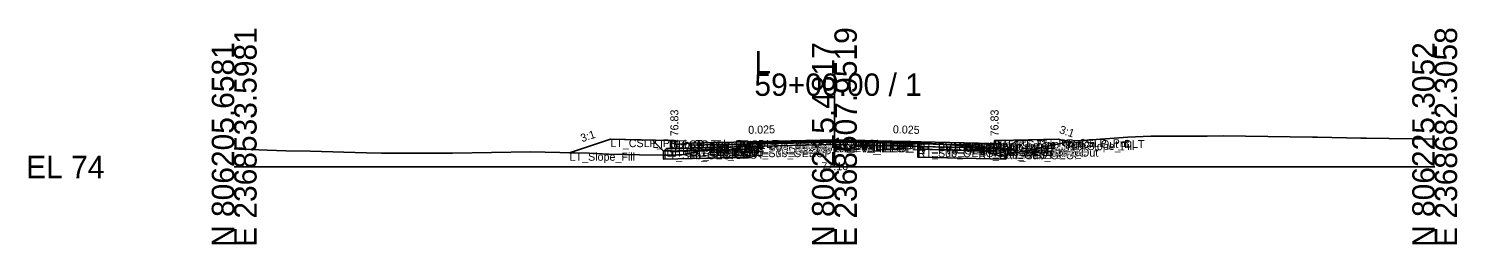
# Model space of a CAD drawing. Extents: x -26 to 8153, y -10 to 9520.
# Drawn here: x 4974.3 to 5152.8, y 7990.3 to 8017.3 of the extents above; entities that cross this region are included whole.
import ezdxf

# ---------------------------------------------------------------- set-up
doc = ezdxf.new("R2010")
doc.units = 0
for name, color, linetype in [('Exist CMT Pavement', 7, 'Continuous'), ('Exist Cross Section Cell', 7, 'Continuous'), ('Exist XS Center Line Elevation Label', 7, 'Continuous'), ('Exist XS Ground Line', 7, 'Continuous'), ('Prop CMT Conc Surface', 7, 'Continuous'), ('Prop CMT Concrete Structures', 7, 'Continuous'), ('Prop CMT Pvmt Course 1', 7, 'Continuous'), ('Prop CMT Pvmt Course 1 CG', 7, 'Continuous'), ('Prop CMT Pvmt Course 1 Wedge', 7, 'Continuous'), ('Prop CMT Pvmt Course 2', 7, 'Continuous'), ('Prop CMT Pvmt Course 2 Wedge', 7, 'Continuous'), ('Prop CMT Pvmt Course 3', 7, 'Continuous'), ('Prop CMT Pvmt Course 3 Wedge', 7, 'Continuous'), ('Prop CMT Pvmt Surface', 7, 'Continuous'), ('Prop CMT Pvmt Wedge Surface 1', 7, 'Continuous'), ('Prop CMT Pvmt Wedge Surface 2', 7, 'Continuous'), ('Prop CMT Pvmt Wedge Surface 3', 7, 'Continuous'), ('Prop CMT Shallow Undercut', 7, 'Continuous'), ('Prop CMT Shallow Undercut Boundary', 7, 'Continuous'), ('Prop CMT Slope Grass', 7, 'Continuous'), ('Prop CMT Subgrade Earthwork', 7, 'Continuous'), ('Prop XS Earthwork Shape', 7, 'Continuous'), ('Prop XS Hydro Elevations', 7, 'Continuous'), ('Prop XS SE Text', 7, 'Continuous'), ('Prop XS Side Slope Text', 7, 'Continuous'), ('Prop XS Subgrade Earthwork', 7, 'Continuous'), ('Scratch_Level_2', 7, 'Continuous'), ('Scratch_Level_6', 7, 'Continuous')]:
    doc.layers.add(name, color=color, linetype=linetype)

msp = doc.modelspace()

# ---------------------------------------------------------------- linework, layer by layer
at = {"layer": 'Exist CMT Pavement'}
for p, q in [((5064.44, 8002.84), (5073.5, 8003.08)), ((5073.5, 8003.08), (5074.68, 8003.11)), ((5074.68, 8003.11), (5075, 8003.1)), ((5075, 8003.1), (5075.67, 8003.1)), ((5075.67, 8003.1), (5085.41, 8003.05))]:
    msp.add_line(p, q, dxfattribs=at)
at = {"layer": 'Exist Cross Section Cell'}
for p, q in [((5075, 8000), (5075, 8011.7)), ((5000, 8000), (5075, 8000)), ((5075, 8000), (5150, 8000))]:
    msp.add_line(p, q, dxfattribs=at)
at = {"layer": 'Exist XS Ground Line'}
for p, q in [((5106.01, 8003.33), (5111.65, 8003.71)), ((5111.65, 8003.71), (5114.55, 8003.84)), ((5114.55, 8003.84), (5121.56, 8003.86)), ((5121.56, 8003.86), (5123.55, 8003.9)), ((5123.55, 8003.9), (5134.72, 8003.73)), ((5134.72, 8003.73), (5135.36, 8003.72)), ((5135.36, 8003.72), (5140.79, 8003.62)), ((5000, 8002.26), (5004.11, 8002.1)), ((5004.11, 8002.1), (5006.47, 8002.03)), ((5006.47, 8002.03), (5009.5, 8001.98)), ((5009.5, 8001.98), (5016.55, 8001.75)), ((5027.28, 8001.72), (5037.01, 8001.91)), ((5037.01, 8001.91), (5044.35, 8001.71)), ((5055.92, 8001.53), (5059.21, 8002.22)), ((5059.21, 8002.22), (5061.62, 8002.83)), ((5061.62, 8002.83), (5064.07, 8002.83)), ((5064.07, 8002.83), (5064.44, 8002.84)), ((5064.44, 8002.84), (5073.5, 8003.08)), ((5073.5, 8003.08), (5074.68, 8003.11)), ((5074.68, 8003.11), (5075, 8003.1)), ((5075, 8003.1), (5075.67, 8003.1)), ((5075.67, 8003.1), (5085.41, 8003.05)), ((5085.41, 8003.05), (5090, 8002.71)), ((5090, 8002.71), (5091.85, 8002.59)), ((5091.85, 8002.59), (5092.6, 8002.44)), ((5092.6, 8002.44), (5094.17, 8001.9)), ((5094.17, 8001.9), (5095.77, 8001.33)), ((5097.4, 8001.71), (5100.23, 8002.33)), ((5100.23, 8002.33), (5102.07, 8002.7)), ((5102.07, 8002.7), (5103.26, 8002.93)), ((5103.26, 8002.93), (5104.8, 8003.29)), ((5104.8, 8003.29), (5106.01, 8003.33)), ((5140.79, 8003.62), (5141.49, 8003.61)), ((5141.49, 8003.61), (5150, 8003.5)), ((5016.55, 8001.75), (5018.41, 8001.74)), ((5018.41, 8001.74), (5026.64, 8001.73)), ((5026.64, 8001.73), (5027.28, 8001.72)), ((5044.35, 8001.71), (5046.82, 8001.62)), ((5046.82, 8001.62), (5050.64, 8001.54)), ((5050.64, 8001.54), (5054.33, 8001.47)), ((5054.33, 8001.47), (5055.32, 8001.51)), ((5055.32, 8001.51), (5055.92, 8001.53)), ((5095.77, 8001.33), (5097.4, 8001.71))]:
    msp.add_line(p, q, dxfattribs=at)
at = {"layer": 'Prop CMT Conc Surface'}
for points in [[(5055, 8002.83), (5055, 8003.33), (5054.5, 8003.33)], [(5057, 8002.96), (5055, 8002.83)], [(5093, 8002.96), (5095, 8002.83)], [(5095, 8002.83), (5095, 8003.33), (5095.5, 8003.33)]]:
    msp.add_lwpolyline(points, dxfattribs=at)
at = {"layer": 'Prop CMT Concrete Structures'}
for points in [[(5057, 8002.96), (5055, 8002.83), (5055, 8003.33), (5054.5, 8003.33)], [(5054.5, 8003.33), (5054.5, 8002.31), (5057, 8002.37)], [(5057, 8002.37), (5057, 8002.96)], [(5093, 8002.96), (5095, 8002.83), (5095, 8003.33), (5095.5, 8003.33)], [(5095.5, 8003.33), (5095.5, 8002.31), (5093, 8002.37)], [(5093, 8002.37), (5093, 8002.96)]]:
    msp.add_lwpolyline(points, dxfattribs=at)
at = {"layer": 'Prop CMT Pvmt Course 1'}
for points in [[(5075, 8003.41), (5057, 8002.96)], [(5057, 8002.96), (5057, 8002.71)], [(5057, 8002.71), (5064.44, 8002.89)], [(5064.44, 8003.02), (5075, 8003.28)], [(5064.44, 8002.89), (5064.44, 8003.02)], [(5075, 8003.16), (5075, 8003.41)], [(5075, 8003.41), (5093, 8002.96)], [(5075, 8003.16), (5075, 8003.41)], [(5075, 8003.28), (5075, 8003.16), (5075, 8003.16)], [(5085.41, 8003.02), (5075, 8003.28)], [(5075, 8003.28), (5075, 8003.16), (5075, 8003.16)], [(5085.41, 8002.9), (5085.41, 8003.02)], [(5093, 8002.71), (5085.41, 8002.9)], [(5093, 8002.96), (5093, 8002.71)]]:
    msp.add_lwpolyline(points, dxfattribs=at)
at = {"layer": 'Prop CMT Pvmt Course 1 CG'}
for points in [[(5057, 8002.37), (5054, 8002.3), (5053.66, 8001.96)], [(5053.66, 8001.96), (5057, 8002.04)], [(5057, 8002.04), (5057, 8002.37)], [(5093, 8002.37), (5096, 8002.3), (5096.34, 8001.96)], [(5093, 8002.04), (5093, 8002.37)], [(5096.34, 8001.96), (5093, 8002.04)]]:
    msp.add_lwpolyline(points, dxfattribs=at)
at = {"layer": 'Prop CMT Pvmt Course 1 Wedge'}
for points in [[(5075, 8003.28), (5064.44, 8003.02)], [(5075, 8003.28), (5085.41, 8003.02)]]:
    msp.add_lwpolyline(points, dxfattribs=at)
at = {"layer": 'Prop CMT Pvmt Course 2'}
for points in [[(5064.44, 8002.89), (5057, 8002.71)], [(5057, 8002.71), (5057, 8002.38)], [(5057, 8002.38), (5064.44, 8002.56)], [(5064.44, 8002.56), (5064.44, 8002.89)], [(5085.41, 8002.57), (5085.41, 8002.9)], [(5085.41, 8002.9), (5093, 8002.71)], [(5093, 8002.38), (5085.41, 8002.57)], [(5093, 8002.71), (5093, 8002.38)]]:
    msp.add_lwpolyline(points, dxfattribs=at)
at = {"layer": 'Prop CMT Pvmt Course 2 Wedge'}
for points in [[(5075, 8003.16), (5064.44, 8002.89)], [(5075, 8003.16), (5085.41, 8002.9)]]:
    msp.add_lwpolyline(points, dxfattribs=at)
at = {"layer": 'Prop CMT Pvmt Course 3'}
for points in [[(5064.44, 8002.56), (5057, 8002.38)], [(5057, 8002.38), (5057, 8002.04)], [(5057, 8002.04), (5064.44, 8002.23)], [(5064.44, 8002.23), (5064.44, 8002.56)], [(5085.41, 8002.57), (5093, 8002.38)], [(5085.41, 8002.23), (5085.41, 8002.57)], [(5093, 8002.04), (5085.41, 8002.23)], [(5093, 8002.38), (5093, 8002.04)]]:
    msp.add_lwpolyline(points, dxfattribs=at)
at = {"layer": 'Prop CMT Pvmt Course 3 Wedge'}
for points in [[(5075, 8002.83), (5064.44, 8002.56)], [(5075, 8002.83), (5085.41, 8002.57)]]:
    msp.add_lwpolyline(points, dxfattribs=at)
at = {"layer": 'Prop CMT Pvmt Surface'}
for points in [[(5075, 8003.41), (5057, 8002.96)], [(5075, 8003.41), (5093, 8002.96)]]:
    msp.add_lwpolyline(points, dxfattribs=at)
at = {"layer": 'Prop CMT Pvmt Wedge Surface 1'}
for points in [[(5057, 8002.71), (5057, 8002.96)], [(5064.44, 8002.89), (5057, 8002.71)], [(5075, 8003.28), (5064.44, 8003.02)], [(5064.44, 8003.02), (5064.44, 8002.89)], [(5075, 8003.28), (5085.41, 8003.02)], [(5085.41, 8003.02), (5085.41, 8002.9)], [(5085.41, 8002.9), (5093, 8002.71)], [(5093, 8002.71), (5093, 8002.96)]]:
    msp.add_lwpolyline(points, dxfattribs=at)
at = {"layer": 'Prop CMT Pvmt Wedge Surface 2'}
for points in [[(5075, 8003.16), (5057, 8002.71)], [(5057, 8002.71), (5057, 8002.96)], [(5075, 8003.16), (5093, 8002.71)], [(5093, 8002.71), (5093, 8002.96)]]:
    msp.add_lwpolyline(points, dxfattribs=at)
at = {"layer": 'Prop CMT Pvmt Wedge Surface 3'}
for points in [[(5057, 8002.38), (5057, 8002.96)], [(5075, 8002.83), (5057, 8002.38)], [(5075, 8002.83), (5093, 8002.38)], [(5093, 8002.38), (5093, 8002.96)]]:
    msp.add_lwpolyline(points, dxfattribs=at)
at = {"layer": 'Prop CMT Shallow Undercut'}
for points in [[(5055.32, 8001.51), (5055.92, 8001.53), (5058.55, 8002.08), (5064.44, 8002.23), (5064.44, 8001.23), (5053.66, 8000.96), (5053.66, 8001.48), (5054.33, 8001.47)], [(5085.41, 8002.23), (5093.82, 8002.02), (5094.17, 8001.9), (5095.77, 8001.33), (5096.34, 8001.46), (5096.34, 8000.96), (5085.41, 8001.23)]]:
    msp.add_lwpolyline(points, close=True, dxfattribs=at)
at = {"layer": 'Prop CMT Shallow Undercut Boundary'}
for p, q in [((5053.66, 8001.96), (5053.66, 8000.96)), ((5064.44, 8002.23), (5064.44, 8001.23)), ((5085.41, 8002.23), (5085.41, 8001.23)), ((5096.34, 8001.96), (5096.34, 8000.96)), ((5053.66, 8000.96), (5064.44, 8001.23)), ((5096.34, 8000.96), (5085.41, 8001.23))]:
    msp.add_line(p, q, dxfattribs=at)
at = {"layer": 'Prop CMT Slope Grass'}
for points in [[(5054.5, 8003.33), (5047, 8003.48), (5041.91, 8001.78)], [(5095.5, 8003.33), (5103, 8003.48), (5104.07, 8003.12)]]:
    msp.add_lwpolyline(points, dxfattribs=at)
at = {"layer": 'Prop CMT Subgrade Earthwork'}
for points in [[(5057, 8002.04), (5053.66, 8001.96), (5052.25, 8003.37)], [(5064.44, 8002.23), (5057, 8002.04)], [(5064.44, 8002.23), (5064.46, 8002.84)], [(5085.41, 8002.23), (5085.4, 8003.05)], [(5085.41, 8002.23), (5093, 8002.04)], [(5093, 8002.04), (5096.34, 8001.96), (5097.75, 8003.37)]]:
    msp.add_lwpolyline(points, dxfattribs=at)
at = {"layer": 'Prop XS Earthwork Shape'}
for points in [[(5052.25, 8003.37), (5047, 8003.48), (5041.91, 8001.78), (5044.35, 8001.71), (5046.82, 8001.62), (5050.64, 8001.54), (5053.66, 8001.48), (5053.66, 8001.96)], [(5053.66, 8001.48), (5053.66, 8000.96), (5064.44, 8001.23), (5064.44, 8002.23), (5058.55, 8002.08), (5055.92, 8001.53), (5055.32, 8001.51), (5054.33, 8001.47)], [(5055.32, 8001.51), (5055.92, 8001.53), (5058.55, 8002.08), (5057, 8002.04), (5053.66, 8001.96), (5053.66, 8001.48), (5054.33, 8001.47)], [(5064.44, 8002.23), (5064.46, 8002.84), (5064.44, 8002.84), (5064.07, 8002.83), (5061.62, 8002.83), (5059.21, 8002.22), (5058.55, 8002.08)], [(5092.6, 8002.44), (5093.82, 8002.02), (5093, 8002.04), (5085.41, 8002.23), (5085.4, 8003.05), (5085.41, 8003.05), (5090, 8002.71), (5091.85, 8002.59)], [(5085.41, 8002.23), (5085.41, 8001.23), (5096.34, 8000.96), (5096.34, 8001.46), (5095.77, 8001.33), (5094.17, 8001.9), (5093.82, 8002.02), (5093, 8002.04)], [(5096.34, 8001.96), (5096.34, 8001.46), (5095.77, 8001.33), (5094.17, 8001.9), (5093.82, 8002.02)], [(5096.34, 8001.96), (5096.34, 8001.46), (5097.4, 8001.71), (5100.23, 8002.33), (5102.07, 8002.7), (5103.26, 8002.93), (5104.07, 8003.12), (5103, 8003.48), (5097.75, 8003.37)]]:
    msp.add_lwpolyline(points, close=True, dxfattribs=at)
at = {"layer": 'Prop XS Subgrade Earthwork'}
for p, q in [((5053.66, 8001.96), (5064.44, 8002.23)), ((5085.41, 8002.23), (5096.34, 8001.96))]:
    msp.add_line(p, q, dxfattribs=at)
at = {"layer": 'Scratch_Level_6'}
for points in [[(5055.32, 8001.51), (5055.92, 8001.53), (5058.55, 8002.08), (5064.44, 8002.23), (5064.44, 8001.23), (5053.66, 8000.96), (5053.66, 8001.48), (5054.33, 8001.47)], [(5085.41, 8002.23), (5093.82, 8002.02), (5094.17, 8001.9), (5095.77, 8001.33), (5096.34, 8001.46), (5096.34, 8000.96), (5085.41, 8001.23)]]:
    msp.add_lwpolyline(points, close=True, dxfattribs=at)

# ---------------------------------------------------------------- texts
at = {"layer": 'Exist Cross Section Cell'}
for s, p in [('E 2368533.5981', (5002.8, 7990)), ('E 2368607.9519', (5077.8, 7990)), ('E 2368682.3058', (5152.8, 7990)), ('N 806205.6581', (5000, 7990)), ('N 806215.4817', (5075, 7990)), ('N 806225.3052', (5150, 7990))]:
    msp.add_text(s, height=2.8, rotation=90, dxfattribs=at).set_placement(p)
for s, p in [('L', (5065, 8011.7)), ('59+00.00 / 1', (5065, 8008.9)), ('EL 74', (4974, 7998.6))]:
    msp.add_text(s, height=2.8, dxfattribs=at).set_placement(p)
at = {"layer": 'Exist XS Center Line Elevation Label'}
msp.add_text('77.10', height=1, dxfattribs=at).set_placement((5073.37, 7999.6))
at = {"layer": 'Prop XS Hydro Elevations'}
for p in [(5055.5, 8003.83), (5095.5, 8003.83)]:
    msp.add_text('76.83', height=1, rotation=90, dxfattribs=at).set_placement(p)
at = {"layer": 'Prop XS SE Text'}
for rotation, p in [(1.4321, (5064.24, 8004.14)), (358.5679, (5082.29, 8004.22))]:
    msp.add_text('0.025', height=1, rotation=rotation, dxfattribs=at).set_placement(p)
at = {"layer": 'Prop XS Side Slope Text'}
for rotation, p in [(18.4349, (5043.46, 8003.09)), (341.5651, (5103.02, 8004.26))]:
    msp.add_text('3:1', height=1, rotation=rotation, dxfattribs=at).set_placement(p)
at = {"layer": 'Scratch_Level_2'}
for s, p in [('LT_Slope_Fill', (5041.91, 8000.78)), ('LT_CSLP_Pnt', (5047, 8002.48)), ('LT_Sub_Trench_Out_DLT', (5052.25, 8002.37)), ('LT_Sub_OEOP', (5053.66, 8000.96)), ('LT_CG1_Shelf_Out', (5054, 8001.3)), ('LT_CG_Top_BOC', (5054.5, 8002.33)), ('LT_CG_Bot_BOC', (5054.5, 8001.31)), ('LT_CG_Top_Face', (5055, 8002.33)), ('LT_CG_Top_Gut', (5055, 8001.83)), ('LT_PV1_OEOT', (5057, 8001.96)), ('LT_PV2_OEOT', (5057, 8001.71)), ('LT_PV3_OEOT', (5057, 8001.38)), ('LT_CG_Bot_IE', (5057, 8001.37)), ('LT_Sub_OEOT', (5057, 8001.04)), ('LT_PV1_OEEOP', (5064.44, 8002.02)), ('LT_PV2_OEEOP', (5064.44, 8001.89)), ('LT_PV_OEEOP_EG', (5064.44, 8001.84)), ('LT_PV3_OEEOP', (5064.44, 8001.56)), ('LT_Sub_OEEOP', (5064.44, 8001.23)), ('LT_PV_Sub_Tie_Out', (5064.46, 8001.84)), ('PV1_PGL', (5075, 8002.41)), ('RT_PV1_IEEOP', (5075, 8002.28)), ('LT_PV1_IEEOP', (5075, 8002.28)), ('RT_PV2_IEEOP', (5075, 8002.16)), ('LT_PV2_IEEOP', (5075, 8002.16)), ('PV2_PGL', (5075, 8002.16)), ('RT_PV_IEEOP_EG', (5075, 8002.1)), ('LT_PV_IEEOP_EG', (5075, 8002.1)), ('RT_PV3_IEEOP', (5075, 8001.83)), ('LT_PV3_IEEOP', (5075, 8001.83)), ('RT_PV_Sub_Tie_Out', (5085.4, 8002.05)), ('RT_PV_OEEOP_EG', (5085.41, 8002.05)), ('RT_PV1_OEEOP', (5085.41, 8002.02)), ('RT_PV2_OEEOP', (5085.41, 8001.9)), ('RT_PV3_OEEOP', (5085.41, 8001.57)), ('RT_Sub_OEEOP', (5085.41, 8001.23)), ('RT_PV1_OEOT', (5093, 8001.96)), ('RT_PV2_OEOT', (5093, 8001.71)), ('RT_PV3_OEOT', (5093, 8001.38)), ('RT_CG_Bot_IE', (5093, 8001.37)), ('RT_Sub_OEOT', (5093, 8001.04)), ('RT_CG_Top_Face', (5095, 8002.33)), ('RT_CG_Top_Gut', (5095, 8001.83)), ('RT_CG_Top_BOC', (5095.5, 8002.33)), ('RT_CG_Bot_BOC', (5095.5, 8001.31)), ('RT_CG1_Shelf_Out', (5096, 8001.3)), ('RT_Sub_OEOP', (5096.34, 8000.96)), ('RT_Sub_Trench_Out_DLT', (5097.75, 8002.37)), ('RT_CSLP_Pnt', (5103, 8002.48)), ('RT_Slope_Fill', (5104.07, 8002.12))]:
    msp.add_text(s, height=1, dxfattribs=at).set_placement(p)

doc.saveas('drawing.dxf')
